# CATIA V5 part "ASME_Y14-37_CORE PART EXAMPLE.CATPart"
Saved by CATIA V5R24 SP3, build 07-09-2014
Part number: CA_ASME_Y14.37_BOND_ASSY-101
Material "Honeycomb": density 40 kg/m3
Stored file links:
  \\NW\Data\MSE-Composites\STEP Interoperability\ExampleData\ASME_Y14.37 Test Parts\ASSEMBLY VERSION\ASME_Y14-37_CORE PART EXAMPLE.CATPart
  C:\Users\jvl2147\Desktop\CompositesCatalog.CATMaterial
  \\Nw\787lib\787-PROCINT-WKG\Dom_SSDBS\DM\!!ShareFileForWritingServices\Composites\Standards and References\ASMEY-14.37\ASMEY-14.37_COMPOSITES.CATMaterial
  C:\Program Files\Dassault Systemes\B25SP2PRALL\win_b64\startup\materials\honeycomb.jpg
  \\Nw\787lib\787-PROCINT-WKG\Dom_SSDBS\DM\!!ShareFileForWritingServices\Composites\Standards and References\ASME Y14.37\PLY TABEL_-1 BOND ASSEMBLY.xlsx
  \\Nw\787lib\787-PROCINT-WKG\Dom_SSDBS\DM\!!ShareFileForWritingServices\Composites\Standards and References\ASME Y14.37\ASME_Y14.37_VALIDATION-PROPERTIES_CORE STIFFENED BOND PART.xlsx.xlsx
  Copy (2) of CA_ASME_Y14.37_CORE-STIFFENED-BOND-PART.CATPart
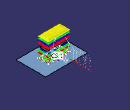
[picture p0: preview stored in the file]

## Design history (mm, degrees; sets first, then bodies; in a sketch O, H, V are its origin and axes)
Parameters
  StandardPlyThickness = 0.254 mm
  `Scale Value` = 100
CompParametersFeature1 "CATCoParametersFeatName": Value 0, Value 45, Value -45, Value 90, Orientations 999.999, Orientations 90
CompStacking1 "Stacking"
CompReviewTools1 "Review tools"
f4a2d38f3ddc11d3a929006094b99c4b_11 "CATTPSSet"
TTRSSet1
Toolside_View1 "CATTPSView"
Set1 "CONSTRUCTION (REF)"
  Sketch1 on XY plane of AxisSystem2, origin (0, 0, 0), H (1, 0, 0), V (0, 1, 0)
    line L1 (-1012.309, 818.5005) -> (1278.0398, 818.5005)
    line L2 (1278.0398, 818.5005) -> (1278.0398, -788.7181)
    line L3 (1278.0398, -788.7181) -> (-1012.309, -788.7181)
    line L4 (-1012.309, -788.7181) -> (-1012.309, 818.5005)
    horizontal: L1 H, L3 H
    vertical: L2 V, L4 V
  Fill1: Boundary Sketch1
  CurvePar1: Offset CompStdContourFeature1, Support Fill1, Offset2 0, Offset1 50.8
  Plane1: type Offset, RefPlane YZ plane of AxisSystem2, Offset -598
  Plane2: type Offset, RefPlane YZ plane of AxisSystem2, Offset -598, reversed
  Plane3: type Offset, RefPlane ZX plane of AxisSystem2, Offset -292
  Plane4: type Offset, RefPlane ZX plane of AxisSystem2, Offset -292, reversed
  MultiSel1
  CompStdContourFeature1 "CATCoStdContourFeatName": SupportSurface Fill1, ClosedSetOfCurves ({intersect ToIntersect1 Plane2, ToIntersect2 Fill1}; {intersect ToIntersect1 Plane3, ToIntersect2 Fill1}; {intersect ToIntersect1 Plane1, ToIntersect2 Fill1}; {intersect ToIntersect1 Plane4, ToIntersect2 Fill1}), ExtrapolDist 0.2
  Plane5: type Offset, RefPlane Plane2, Offset 254, reversed
  Intersect1: ToIntersect1 Plane5, ToIntersect2 Fill1
  Plane6: type Offset, RefPlane Plane1, Offset 254
  Intersect2: ToIntersect1 Plane6, ToIntersect2 Fill1
  Plane7: type Offset, RefPlane ZX plane of AxisSystem2, Offset -50.8
  CurvePar2: Offset CompStdContourFeature1, Offset2 0, Offset1 139.7
  Point1: (0, 0, 0), in AxisSystem2
  AxisSystem1: origin (0, 0, -127), X (1, 0, 0), Y (0, 1, 0), Z (0, 0, 1)
  Point2: (215.6851, 77.4411, 0)
  Point3: type OnCurve, Support edge [ZX plane of AxisSystem2 | YZ plane of AxisSystem2], Length 127
  Point4: type OnPlane, Support Join1, H -130.714, V 273.957, Direction (1, 0, 0)
  Split1: ToCut Circle1, Cutting {intersect ToIntersect1 Plane4, ToIntersect2 Fill1}
  Circle1: type CtrRad, Start 0, End 180, Center Point4, Support Join1, Radius 76.2, FirstDirection (1, 0, 0)
Set2 "ENGINEERING GEOMETRY"
  Join1 "TOOLSIDE SURFACE": Elements Fill1
  AxisSystem2 "PLY ORIENTATION COORDINATE SYSTEM": origin (0, 0, 0), X (1, 0, 0), Y (0, 1, 0), Z (0, 0, 1)
Set3 "EXPLODED PLIES VIEW (REF)"
  CLDGeom1 "PLY 1:10745:0"
  CLDGeom2 "PLY 2:10745:0"
  CLDGeom3 "PLY 3:10721:0"
  CLDGeom4 "PLY 4:10721:45"
  CLDGeom5 "PLY 5:10721:0"
  CLDGeom6 "PLY 6:10721:45"
  CLDGeom7 "PLY 7:10679:-45"
  DatumSurface1 "Core -103"
  CLDGeom8 "PLY 8:10679:0"
  CLDGeom9 "PLY 9:10721:0"
  CLDGeom10 "PLY 10:10721:-45"
  CLDGeom11 "PLY 11:10721:45"
  CLDGeom12 "PLY 12:10721:90"
Body1 "ASME_Y14.37_CORE_PART-101 (REF)" (main body)
  Solid1 "ASME_Y14.37_CORE_PART-101": solid without history
Body2 "CORE -103"
  CompCoreSolidFormGeometry1 "Geometry_8": Curves CurvePar1, ReferenceSurface Fill1, VariableOffsets 0, VariableSlopes 20, BasicHeight 25.4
